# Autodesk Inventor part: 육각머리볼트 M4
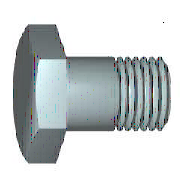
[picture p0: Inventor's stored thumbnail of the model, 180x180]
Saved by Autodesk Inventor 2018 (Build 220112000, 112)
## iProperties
IsCustomPart: 1
Created: 2012-02
Part Number: 육각머리볼트 M4
Material: 강철, 연강
Description: 6각 머리 볼트 및 6각 머리 나사
Document SubType Name: Modeling
Standard: KS B 1002
Designer: mduedu
Standards Organization: KS
Language: ko-KR
Size Designation: A + B M4 x 16
Categories: <MemberInstance><Categories><Category DisplayName="조임쇠" InternalName="e4da775c-781d-43d5-af7c-5136215cf5a6" Mnemonic="FSTN"><Category DisplayName="볼트" InternalN
Density: 1 g/cm^3
Appearance: 강철
Author: mduedu
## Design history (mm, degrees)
sketch "스케치1"
  geometry: L1 (0, 2.94)-(0, 2); L2 (2.1, 2)-(16, 2); L3 (16, 2)-(16, 0); L4 (16, 0)-(-0.4, 0); L5 (-3.68, 0)-(19.28, 0) reference; L6 (-0.4, 0)-(-0.4, 2.94); L7 (-0.4, 2.94)-(0, 2.94); L8 (2.1, 2)-(1.67, 2); L9 (1.67, 2)-(0, 2); L10 (0, -0.588)-(0, 3.528) reference
  constraints: 16 end point, 2 collinear, 2 perpendicular, 1 parallel
  dimensions: "d0" = 16 distance between parallel lines of L3 L1 (= NLG); "d1" = 13.9 distance from line of L2.start L3 (= GEL); "d2" = 4 diameter of L2 L4 (= GD); "d9" = 0.4001 distance between parallel lines of L6 L1 (computed from SD); "d10" = 5.88 diameter of L7 L4 (= SD2); "d13" = 0.42952 distance of L2.start L8.end (computed from GAL); "d14" = 4 diameter of L9 L4 (= BDM)
revolve "본체" sketch "스케치1" stored, may be unused: angle "d12" = 90 deg
sketch "스케치2"
  geometry: L1 (0, 4.041)-(3.5, 2.021); L2 (3.5, 2.021)-(3.5, -2.021); L3 (3.5, -2.021)-(0, -4.041); L4 (0, -4.041)-(-3.5, -2.021); L5 (-3.5, -2.021)-(-3.5, 2.021); L6 (-3.5, 2.021)-(0, 4.041); 2 further points
  constraints: 12 end point, 1 coincident, 1 vertical, 11 other
  dimensions: "d11" = 7 distance between parallel lines of L5 L2 (= SW)
extrude "머리" join sketch "스케치2" distance "d3" = 2.4 (= KOH - SD); taper "d4" = 0 deg
sketch "스케치4"
  geometry: L1 (-2.8, 3.5)-(-2.8, 4.041); L2 (-2.8, 4.041)-(-2.487, 4.041); L3 (-2.487, 4.041)-(-2.8, 3.5); L4 (-3.28, 0)-(0.08, 0) reference; L5 (-0.4, 4.041)-(-2.8, 4.041) reference; L6 (-2.8, 2.021)-(-2.8, 4.041) reference
  constraints: 6 end point, 2 collinear, 1 perpendicular, 1 vertical
  dimensions: "d5" = 30 deg angle of L3 L1 (= ANG1); "d19" = 7 diameter of L1.start L4 (= SW0)
revolve "모따기1" sketch "스케치4" stored, may be unused: angle "d21" = 90 deg
workplane "Work Plane1"
body "Solid1"
feature "스레드" dims "d15" = 13.9 (= GEL), "d16" = 0
chamfer "모따기2" distance "d6" = 0.42941 (= -0.5 x SPD + 0.5 x GD); stored, may be unused: second distance "d7" = 0.42952 (computed from GUL), angle "d55" = 45 deg
other parameters: "NLG" = 16 [user parameter; used in 1 equation term], "GD" = 4 (= NND) [user parameter; used in 2 equation terms], "BDM" = 4 (= NND) [user parameter; used in 1 equation term], "KOH" = 2.8 [user parameter; used in 1 equation term], "GEL" = 13.9 [user parameter; used in 2 equation terms], "SW" = 7 [user parameter; used in 3 equation terms], "SW0" = 7 (= SW) [user parameter; used in 1 equation term], "SPD" = 3.14117 (= NND - 1.2269 x PTC) [user parameter; used in 1 equation term], "SD2" = 5.88 (= SDH) [user parameter; used in 1 equation term], "SD" = 0.4 [user parameter; used in 2 equation terms], "ANG1" = 30 deg [user parameter; used in 1 equation term], "GAL" = 0.42941 (= 0.61345 x PTC) [user parameter; used in 1 equation term], "GUL" = 0.42941 (= 0.61345 x PTC) [user parameter; used in 1 equation term], "d8" = 0, "RR" = 0.2 [user parameter], "d57" = 0, "d58" = 0, "TPU" = 14.28571 (computed from PTC) [user parameter], "GD1" = 3.14117 (= THREADDIA - 1.2269 x PTC) [user parameter], "THREADDIA" = 4 [user parameter; used in 1 equation term], "SDH" = 5.88 [user parameter; used in 1 equation term], "SDHG" = 2.1 [user parameter], "TOA" = 30 deg [user parameter], "PTC" = 0.7 [user parameter; used in 5 equation terms], "NND" = 4 [user parameter; used in 3 equation terms], "E0" = 8.085 (= 1.155 x SW) [user parameter]
